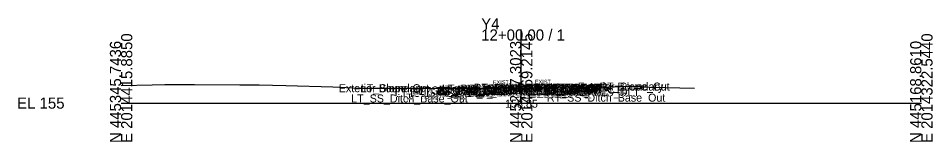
# Model space of a CAD drawing. Extents: x -26 to 203, y -10 to 4021.
# Drawn here: x -25.7 to 202.8, y 3990.3 to 4021.3 of the extents above; entities that cross this region are included whole.
import ezdxf

# ---------------------------------------------------------------- set-up
doc = ezdxf.new("R2010")
doc.units = 0
for name, color, linetype in [('Default', 7, 'Continuous'), ('Exist Cross Section Cell', 7, 'Continuous'), ('Exist XS Center Line Elevation Label', 7, 'Continuous'), ('Exist XS Ground Line', 7, 'Continuous'), ('Prop CMT Pvmt Surface Shoulder', 7, 'Continuous'), ('Prop CMT Shld Paved Course 1', 7, 'Continuous'), ('Prop XS SE Text', 7, 'Continuous'), ('Scratch_Level_0', 7, 'Continuous')]:
    doc.layers.add(name, color=color, linetype=linetype)

msp = doc.modelspace()

# ---------------------------------------------------------------- linework, layer by layer
at = {"layer": 'Exist Cross Section Cell'}
for p, q in [((100, 4000), (100, 4018.48)), ((0, 4000), (100, 4000)), ((100, 4000), (200, 4000))]:
    msp.add_line(p, q, dxfattribs=at)
at = {"layer": 'Exist XS Ground Line'}
msp.add_lwpolyline([(0, 4004.42), (7.76, 4004.56), (10.96, 4004.64), (12.33, 4004.66), (18.33, 4004.7), (29.66, 4004.62), (34.48, 4004.55), (41.14, 4004.42), (52.89, 4004.07), (59.66, 4003.74), (60, 4003.73), (75.71, 4003.74), (82.07, 4003.7), (89.43, 4003.67), (99.47, 4003.84), (100.03, 4003.85), (100.34, 4003.85), (105.68, 4003.85), (111.05, 4003.86), (114.84, 4003.91), (128.82, 4004.22), (132.25, 4004.02), (143.33, 4003.77)], dxfattribs=at)
at = {"layer": 'Prop CMT Pvmt Surface Shoulder'}
msp.add_lwpolyline([(110.4, 4003.85), (110.4, 4003.85)], dxfattribs=at)
at = {"layer": 'Prop CMT Shld Paved Course 1'}
msp.add_lwpolyline([(110.4, 4003.85), (110.4, 4003.85)], dxfattribs=at)

# ---------------------------------------------------------------- texts
at = {"layer": 'Default'}
msp.add_text('-', height=0.0001, dxfattribs=at).set_placement((0, 4000))
at = {"layer": 'Exist Cross Section Cell'}
for s, p in [('Y4', (90, 4018.48)), ('12+00.00 / 1', (90, 4015.68)), ('EL 155', (-26, 3998.6))]:
    msp.add_text(s, height=2.8, dxfattribs=at).set_placement(p)
for s, p in [('N 445345.7436', (0, 3990)), ('E 2014415.8850', (2.8, 3990)), ('N 445257.3023', (100, 3990)), ('E 2014369.2145', (102.8, 3990)), ('N 445168.8610', (200, 3990)), ('E 2014322.5440', (202.8, 3990))]:
    msp.add_text(s, height=2.8, rotation=90, dxfattribs=at).set_placement(p)
at = {"layer": 'Exist XS Center Line Elevation Label'}
msp.add_text('158.85', height=2, dxfattribs=at).set_placement((95.98, 3998.85))
at = {"layer": 'Prop XS SE Text'}
for rotation, p in [(1.1458, (92.93, 4004.71)), (360, (103.43, 4004.85))]:
    msp.add_text('EXIST.', height=1, rotation=rotation, dxfattribs=at).set_placement(p)
at = {"layer": 'Scratch_Level_0'}
for s, p in [('Exterior Boundary', (54.41, 4002.74)), ('LT_Slope_Cut', (59.91, 4002.74)), ('LT_GS_OS_CTL', (72.8, 4002.16)), ('LT_PS3_Shelf_Out', (74.32, 4002.04)), ('LT_PS3_OEOP', (79.07, 4002.05)), ('LT_PS2_OEOP', (79.41, 4002.39)), ('LT_PV2_OEOT', (79.6, 4002.39)), ('LT_PV3_OEOT', (79.6, 4002.06)), ('LT_PV1_OEOT', (80.17, 4002.64)), ('LT_PS1_OEOP', (80.23, 4002.64)), ('RT_PV_IEEOP_EG', (88.14, 4002.85)), ('LT_Sub_OEEOP', (89.21, 4001.94)), ('LT_PV2_OEEOP', (89.31, 4002.6)), ('LT_PV3_OEEOP', (89.31, 4002.27)), ('LT_PV1_OEEOP', (89.87, 4002.73)), ('RT_PV2_IEEOP', (89.91, 4002.6)), ('RT_PV3_IEEOP', (89.91, 4002.27)), ('LT_PV2_IEEOP', (89.95, 4002.6)), ('RT_PV1_IEEOP', (90.47, 4002.73)), ('LT_PV1_IEEOP', (90.52, 4002.73)), ('PV2_PGL', (93.91, 4002.6)), ('PV1_PGL', (94.47, 4002.85)), ('RT_Sub_Trench_Out', (95.99, 4001.91)), ('RT_Sub Tie Out', (96.69, 4002.85)), ('RT_PV_OEEOP_EG', (96.89, 4002.85)), ('RT_PS3_Shelf_Out', (97.43, 4002.25)), ('RT_Sub_OEEOP', (98.56, 4001.94)), ('RT_PV2_OEEOP', (98.66, 4002.6)), ('RT_PV3_OEEOP', (98.66, 4002.27)), ('RT_PV1_OEEOP', (99.22, 4002.73)), ('RT_Sub_OEOT', (100.43, 4001.94)), ('RT_PV2_OEOT', (100.52, 4002.6)), ('RT_PV3_OEOT', (100.52, 4002.27)), ('RT_PS2_OEOP', (100.84, 4002.6)), ('RT_PV1_OEOT', (101.09, 4002.85)), ('RT_PS1_OEOP', (101.15, 4002.85)), ('RT_PS3_OEOP', (101.18, 4002.26)), ('RT_GS_OS_CTL', (105.72, 4002.37)), ('Exterior Boundary', (114.1, 4003.15)), ('RT_Slope_Cut', (119.55, 4003.15)), ('LT_SS_Ditch_Base_Out', (57.51, 4000.16)), ('LT_Sub_OSS_DLT', (68.41, 4001.56)), ('LT_Sub_Trench_Out', (72.2, 4001.7)), ('LT_Sub_OEOT', (79.51, 4001.72)), ('RT_Sub_OSS_DLT', (106.17, 4001.77)), ('RT_SS_Ditch_Base_Out', (106.43, 4000.37))]:
    msp.add_text(s, height=2, dxfattribs=at).set_placement(p)

doc.saveas('drawing.dxf')
